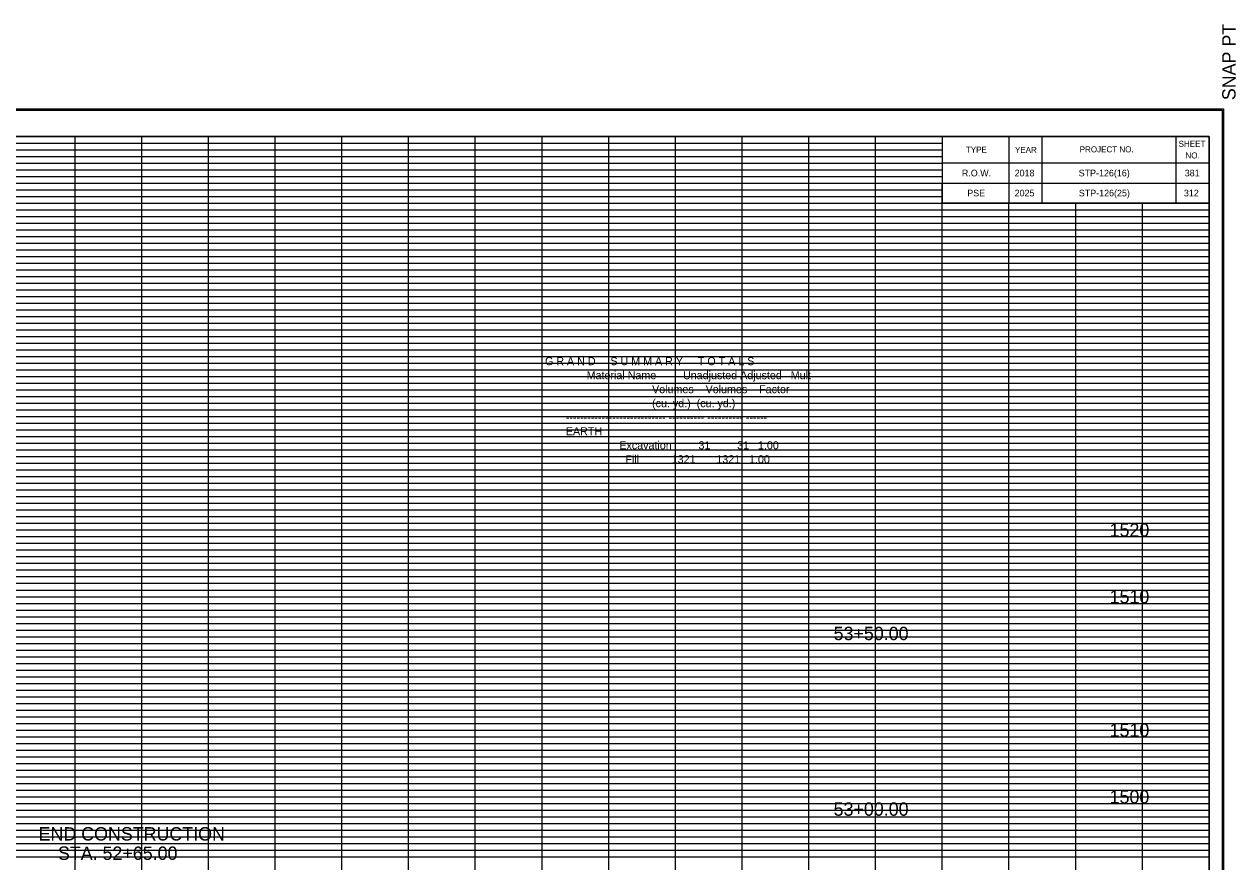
# Model space of a CAD drawing. Extents: x 980 to 1324, y 978 to 1497.
# Drawn here: x 1142.4 to 1324, y 1371.3 to 1496.8 of the extents above; entities that cross this region are included whole.
import ezdxf

# ---------------------------------------------------------------- set-up
doc = ezdxf.new("R2010")
doc.units = 0
for name, color, linetype in [('DESIGN - SCRATCH - User 1', 7, 'Continuous'), ('DESIGN - SHEET - Corner Text', 7, 'Continuous'), ('DESIGN - SHEET - Light Grid', 7, 'Continuous'), ('DESIGN - SHEET - Linework', 7, 'Continuous'), ('DESIGN - SHEET - Plot Shape', 7, 'Continuous'), ('DESIGN - TYPICAL - Text', 7, 'Continuous')]:
    doc.layers.add(name, color=color, linetype=linetype)

# ---------------------------------------------------------------- blocks, each defined once
blk = doc.blocks.new('XSTSHT')
at = {"layer": 'DESIGN - SCRATCH - User 1'}
for p, q in [((28.5, 20.45), (28.5, 20.45)), ((29.24, 20.45), (29.24, 20.45)), ((30.49, 20.45), (30.49, 20.45)), ((31.74, 20.45), (31.74, 20.45)), ((28.5, 20.15), (28.5, 20.15)), ((29.24, 20.15), (29.24, 20.15)), ((30.49, 20.15), (30.49, 20.15)), ((31.74, 20.15), (31.74, 20.15))]:
    blk.add_line(p, q, dxfattribs=at)
at = {"layer": 'DESIGN - SHEET - Light Grid'}
for p, q in [((8, 20.9), (16, 20.9)), ((16, 20.9), (24, 20.9)), ((24, 20.9), (28, 20.9)), ((8, 20.8), (16, 20.8)), ((16, 20.8), (24, 20.8)), ((24, 20.8), (28, 20.8)), ((8, 20.7), (16, 20.7)), ((8, 20.6), (16, 20.6)), ((16, 20.7), (24, 20.7)), ((16, 20.6), (24, 20.6)), ((24, 20.7), (28, 20.7)), ((24, 20.6), (28, 20.6)), ((8, 20.5), (16, 20.5)), ((8, 20.4), (16, 20.4)), ((16, 20.5), (24, 20.5)), ((16, 20.4), (24, 20.4)), ((24, 20.5), (28, 20.5)), ((24, 20.4), (28, 20.4)), ((8, 20.3), (16, 20.3)), ((8, 20.2), (16, 20.2)), ((16, 20.3), (24, 20.3)), ((16, 20.2), (24, 20.2)), ((24, 20.3), (28, 20.3)), ((24, 20.2), (28, 20.2)), ((8, 20.1), (16, 20.1)), ((16, 20.1), (24, 20.1)), ((24, 20.1), (28, 20.1)), ((8, 19.9), (16, 19.9)), ((8, 19.8), (16, 19.8)), ((16, 19.9), (24, 19.9)), ((16, 19.8), (24, 19.8)), ((24, 19.9), (32, 19.9)), ((24, 19.8), (32, 19.8)), ((8, 19.7), (16, 19.7)), ((16, 19.7), (24, 19.7)), ((24, 19.7), (32, 19.7)), ((8, 19.6), (16, 19.6)), ((8, 19.5), (16, 19.5)), ((16, 19.6), (24, 19.6)), ((16, 19.5), (24, 19.5)), ((24, 19.6), (32, 19.6)), ((24, 19.5), (32, 19.5)), ((8, 19.4), (16, 19.4)), ((8, 19.3), (16, 19.3)), ((16, 19.4), (24, 19.4)), ((16, 19.3), (24, 19.3)), ((24, 19.4), (32, 19.4)), ((24, 19.3), (32, 19.3)), ((8, 19.2), (16, 19.2)), ((8, 19.1), (16, 19.1)), ((16, 19.2), (24, 19.2)), ((16, 19.1), (24, 19.1)), ((24, 19.2), (32, 19.2)), ((24, 19.1), (32, 19.1)), ((8, 18.9), (16, 18.9)), ((16, 18.9), (24, 18.9)), ((24, 18.9), (32, 18.9)), ((8, 18.8), (16, 18.8)), ((16, 18.8), (24, 18.8)), ((24, 18.8), (32, 18.8)), ((8, 18.7), (16, 18.7)), ((8, 18.6), (16, 18.6)), ((16, 18.7), (24, 18.7)), ((16, 18.6), (24, 18.6)), ((24, 18.7), (32, 18.7)), ((24, 18.6), (32, 18.6)), ((8, 18.5), (16, 18.5)), ((8, 18.4), (16, 18.4)), ((16, 18.5), (24, 18.5)), ((16, 18.4), (24, 18.4)), ((24, 18.5), (32, 18.5)), ((24, 18.4), (32, 18.4)), ((8, 18.3), (16, 18.3)), ((8, 18.2), (16, 18.2)), ((16, 18.3), (24, 18.3)), ((16, 18.2), (24, 18.2)), ((24, 18.3), (32, 18.3)), ((24, 18.2), (32, 18.2)), ((8, 18.1), (16, 18.1)), ((16, 18.1), (24, 18.1)), ((24, 18.1), (32, 18.1)), ((8, 17.9), (16, 17.9)), ((8, 17.8), (16, 17.8)), ((16, 17.9), (24, 17.9)), ((16, 17.8), (24, 17.8)), ((24, 17.9), (32, 17.9)), ((24, 17.8), (32, 17.8)), ((8, 17.7), (16, 17.7)), ((16, 17.7), (24, 17.7)), ((24, 17.7), (32, 17.7)), ((8, 17.6), (16, 17.6)), ((8, 17.5), (16, 17.5)), ((16, 17.6), (24, 17.6)), ((16, 17.5), (24, 17.5)), ((24, 17.6), (32, 17.6)), ((24, 17.5), (32, 17.5)), ((8, 17.4), (16, 17.4)), ((8, 17.3), (16, 17.3)), ((16, 17.4), (24, 17.4)), ((16, 17.3), (24, 17.3)), ((24, 17.4), (32, 17.4)), ((24, 17.3), (32, 17.3)), ((8, 17.2), (16, 17.2)), ((8, 17.1), (16, 17.1)), ((16, 17.2), (24, 17.2)), ((16, 17.1), (24, 17.1)), ((24, 17.2), (32, 17.2)), ((24, 17.1), (32, 17.1)), ((8, 16.9), (16, 16.9)), ((16, 16.9), (24, 16.9)), ((24, 16.9), (32, 16.9)), ((8, 16.8), (16, 16.8)), ((16, 16.8), (24, 16.8)), ((24, 16.8), (32, 16.8)), ((8, 16.7), (16, 16.7)), ((8, 16.6), (16, 16.6)), ((16, 16.7), (24, 16.7)), ((16, 16.6), (24, 16.6)), ((24, 16.7), (32, 16.7)), ((24, 16.6), (32, 16.6)), ((8, 16.5), (16, 16.5)), ((8, 16.4), (16, 16.4)), ((16, 16.5), (24, 16.5)), ((16, 16.4), (24, 16.4)), ((24, 16.5), (32, 16.5)), ((24, 16.4), (32, 16.4)), ((8, 16.3), (16, 16.3)), ((8, 16.2), (16, 16.2)), ((16, 16.3), (24, 16.3)), ((16, 16.2), (24, 16.2)), ((24, 16.3), (32, 16.3)), ((24, 16.2), (32, 16.2)), ((8, 16.1), (16, 16.1)), ((16, 16.1), (24, 16.1)), ((24, 16.1), (32, 16.1)), ((8, 15.9), (16, 15.9)), ((16, 15.9), (24, 15.9)), ((24, 15.9), (32, 15.9)), ((8, 15.8), (16, 15.8)), ((8, 15.7), (16, 15.7)), ((16, 15.8), (24, 15.8)), ((16, 15.7), (24, 15.7)), ((24, 15.8), (32, 15.8)), ((24, 15.7), (32, 15.7)), ((8, 15.6), (16, 15.6)), ((8, 15.5), (16, 15.5)), ((16, 15.6), (24, 15.6)), ((16, 15.5), (24, 15.5)), ((24, 15.6), (32, 15.6)), ((24, 15.5), (32, 15.5)), ((8, 15.4), (16, 15.4)), ((8, 15.3), (16, 15.3)), ((16, 15.4), (24, 15.4)), ((16, 15.3), (24, 15.3)), ((24, 15.4), (32, 15.4)), ((24, 15.3), (32, 15.3)), ((8, 15.2), (16, 15.2)), ((8, 15.1), (16, 15.1)), ((16, 15.2), (24, 15.2)), ((16, 15.1), (24, 15.1)), ((24, 15.2), (32, 15.2)), ((24, 15.1), (32, 15.1)), ((8, 14.9), (16, 14.9)), ((16, 14.9), (24, 14.9)), ((24, 14.9), (32, 14.9)), ((8, 14.8), (16, 14.8)), ((16, 14.8), (24, 14.8)), ((24, 14.8), (32, 14.8)), ((8, 14.7), (16, 14.7)), ((8, 14.6), (16, 14.6)), ((16, 14.7), (24, 14.7)), ((16, 14.6), (24, 14.6)), ((24, 14.7), (32, 14.7)), ((24, 14.6), (32, 14.6)), ((8, 14.5), (16, 14.5)), ((8, 14.4), (16, 14.4)), ((16, 14.5), (24, 14.5)), ((16, 14.4), (24, 14.4)), ((24, 14.5), (32, 14.5)), ((24, 14.4), (32, 14.4)), ((8, 14.3), (16, 14.3)), ((8, 14.2), (16, 14.2)), ((16, 14.3), (24, 14.3)), ((16, 14.2), (24, 14.2)), ((24, 14.3), (32, 14.3)), ((24, 14.2), (32, 14.2)), ((8, 14.1), (16, 14.1)), ((16, 14.1), (24, 14.1)), ((24, 14.1), (32, 14.1)), ((8, 13.9), (16, 13.9)), ((16, 13.9), (24, 13.9)), ((24, 13.9), (32, 13.9)), ((8, 13.8), (16, 13.8)), ((8, 13.7), (16, 13.7)), ((16, 13.8), (24, 13.8)), ((16, 13.7), (24, 13.7)), ((24, 13.8), (32, 13.8)), ((24, 13.7), (32, 13.7)), ((8, 13.6), (16, 13.6)), ((8, 13.5), (16, 13.5)), ((16, 13.6), (24, 13.6)), ((16, 13.5), (24, 13.5)), ((24, 13.6), (32, 13.6)), ((24, 13.5), (32, 13.5)), ((8, 13.4), (16, 13.4)), ((8, 13.3), (16, 13.3)), ((16, 13.4), (24, 13.4)), ((16, 13.3), (24, 13.3)), ((24, 13.4), (32, 13.4)), ((24, 13.3), (32, 13.3)), ((8, 13.2), (16, 13.2)), ((8, 13.1), (16, 13.1)), ((16, 13.2), (24, 13.2)), ((16, 13.1), (24, 13.1)), ((24, 13.2), (32, 13.2)), ((24, 13.1), (32, 13.1)), ((8, 12.9), (16, 12.9)), ((16, 12.9), (24, 12.9)), ((24, 12.9), (32, 12.9)), ((8, 12.8), (16, 12.8)), ((16, 12.8), (24, 12.8)), ((24, 12.8), (32, 12.8)), ((8, 12.7), (16, 12.7)), ((8, 12.6), (16, 12.6)), ((16, 12.7), (24, 12.7)), ((16, 12.6), (24, 12.6)), ((24, 12.7), (32, 12.7)), ((24, 12.6), (32, 12.6)), ((8, 12.5), (16, 12.5)), ((8, 12.4), (16, 12.4)), ((16, 12.5), (24, 12.5)), ((16, 12.4), (24, 12.4)), ((24, 12.5), (32, 12.5)), ((24, 12.4), (32, 12.4)), ((8, 12.3), (16, 12.3)), ((8, 12.2), (16, 12.2)), ((16, 12.3), (24, 12.3)), ((16, 12.2), (24, 12.2)), ((24, 12.3), (32, 12.3)), ((24, 12.2), (32, 12.2)), ((8, 12.1), (16, 12.1)), ((16, 12.1), (24, 12.1)), ((24, 12.1), (32, 12.1)), ((8, 11.9), (16, 11.9)), ((16, 11.9), (24, 11.9)), ((24, 11.9), (32, 11.9)), ((8, 11.8), (16, 11.8)), ((8, 11.7), (16, 11.7)), ((16, 11.8), (24, 11.8)), ((16, 11.7), (24, 11.7)), ((24, 11.8), (32, 11.8)), ((24, 11.7), (32, 11.7)), ((8, 11.6), (16, 11.6)), ((8, 11.5), (16, 11.5)), ((16, 11.6), (24, 11.6)), ((16, 11.5), (24, 11.5)), ((24, 11.6), (32, 11.6)), ((24, 11.5), (32, 11.5)), ((8, 11.4), (16, 11.4)), ((8, 11.3), (16, 11.3)), ((16, 11.4), (24, 11.4)), ((16, 11.3), (24, 11.3)), ((24, 11.4), (32, 11.4)), ((24, 11.3), (32, 11.3)), ((8, 11.2), (16, 11.2)), ((8, 11.1), (16, 11.1)), ((16, 11.2), (24, 11.2)), ((16, 11.1), (24, 11.1)), ((24, 11.2), (32, 11.2)), ((24, 11.1), (32, 11.1)), ((8, 10.9), (16, 10.9)), ((16, 10.9), (24, 10.9)), ((24, 10.9), (32, 10.9)), ((8, 10.8), (16, 10.8)), ((16, 10.8), (24, 10.8)), ((24, 10.8), (32, 10.8)), ((8, 10.7), (16, 10.7)), ((8, 10.6), (16, 10.6)), ((16, 10.7), (24, 10.7)), ((16, 10.6), (24, 10.6)), ((24, 10.7), (32, 10.7)), ((24, 10.6), (32, 10.6)), ((8, 10.5), (16, 10.5)), ((8, 10.4), (16, 10.4)), ((16, 10.5), (24, 10.5)), ((16, 10.4), (24, 10.4)), ((24, 10.5), (32, 10.5)), ((24, 10.4), (32, 10.4)), ((8, 10.3), (16, 10.3)), ((8, 10.2), (16, 10.2)), ((16, 10.3), (24, 10.3)), ((16, 10.2), (24, 10.2)), ((24, 10.3), (32, 10.3)), ((24, 10.2), (32, 10.2))]:
    blk.add_line(p, q, dxfattribs=at)
at = {"layer": 'DESIGN - SHEET - Linework'}
for p, q in [((-1.823, 21.414), (32.217, 21.414)), ((32.217, 21.414), (32.217, -0.414)), ((15, 0), (15, 21)), ((16, 0), (16, 21)), ((17, 0), (17, 21)), ((18, 0), (18, 21)), ((19, 0), (19, 21)), ((20, 0), (20, 21)), ((21, 0), (21, 21)), ((22, 0), (22, 21)), ((23, 0), (23, 21)), ((24, 0), (24, 21)), ((25, 0), (25, 21)), ((26, 0), (26, 21)), ((27, 0), (27, 21)), ((0, 20), (28, 20)), ((28, 0), (28, 20)), ((29, 0), (29, 20)), ((30, 0), (30, 20)), ((31, 0), (31, 20)), ((0, 19), (32, 19)), ((0, 18), (32, 18)), ((0, 17), (32, 17)), ((0, 16), (32, 16)), ((0, 15), (32, 15)), ((0, 14), (32, 14)), ((0, 13), (32, 13)), ((0, 12), (32, 12)), ((0, 11), (32, 11))]:
    blk.add_line(p, q, dxfattribs=at)
for points in [[(0, 21), (0, 0), (32, 0), (32, 21), (0, 21)], [(28, 21), (28, 20), (32, 20), (32, 21), (31.5, 21), (31.5, 20), (29.5, 20), (29.5, 21), (29, 21), (29, 20), (32, 20), (28, 20), (28, 20.3), (32, 20.3), (32, 20.6), (28, 20.6)]]:
    blk.add_lwpolyline(points, dxfattribs=at)
at = {"layer": 'DESIGN - SHEET - Plot Shape'}
for points in [[(-1.803, 21.394), (32.197, 21.394), (32.197, -0.394), (-1.803, -0.394)], [(-0.85, 21), (32, 21), (32, -0.25), (-0.85, -0.25)]]:
    blk.add_lwpolyline(points, close=True, dxfattribs=at)
at = {"layer": 'DESIGN - SHEET - Corner Text'}
blk.add_text('  SNAP PT', height=0.2, rotation=90, dxfattribs=at).set_placement((32.397, 21.394))
for s, p in [('SHEET', (31.543, 20.843)), ('TYPE', (28.354, 20.756)), ('YEAR', (29.09, 20.752)), ('PROJECT NO.', (30.06, 20.76)), ('NO.', (31.646, 20.669))]:
    blk.add_text(s, height=0.09, dxfattribs=at).set_placement(p)

msp = doc.modelspace()

# ---------------------------------------------------------------- linework, layer by layer
at = {"layer": 'DESIGN - SHEET - Plot Shape'}
msp.add_lwpolyline([(991.5, 1267.5), (1320, 1267.5), (1320, 1480), (991.5, 1480)], close=True, dxfattribs=at)

# ---------------------------------------------------------------- block references
at = {"layer": 'DESIGN - TYPICAL - Text', "xscale": 10, "yscale": 10}
msp.add_blockref('XSTSHT', (1000, 1270), dxfattribs=at)

# ---------------------------------------------------------------- texts
at = {"layer": 'DESIGN - SHEET - Corner Text'}
for s, p in [('R.O.W.', (1282.94, 1474)), ('2018', (1290.85, 1474)), ('STP-126(16)', (1300.45, 1474)), ('381', (1316.35, 1474)), ('PSE', (1283.75, 1471)), ('2025', (1290.85, 1471)), ('STP-126(25)', (1300.47, 1471)), ('312', (1316.22, 1471))]:
    msp.add_text(s, height=1, dxfattribs=at).set_placement(p)
at = {"layer": 'DESIGN - TYPICAL - Text'}
for s, height, p in [(' G R A N D     S U M M A R Y     T O T A L S', 1.2, (1220, 1445.7)), ('               Material Name         Unadjusted Adjusted   Mult', 1.2, (1220, 1443.6)), ('                                     Volumes    Volumes    Factor', 1.2, (1220, 1441.5)), ('                                     (cu. yd.)  (cu. yd.)', 1.2, (1220, 1439.4)), ('        ---------------------------- ---------- ---------- ------', 1.2, (1220, 1437.3)), ('        EARTH', 1.2, (1220, 1435.2)), ('                          Excavation         31         31   1.00', 1.2, (1220, 1433.1)), ('                            Fill           1321       1321   1.00', 1.2, (1220, 1431)), ('     1520     ', 2, (1301.37, 1420)), ('     1510     ', 2, (1301.37, 1410)), ('     53+50.00     ', 2, (1260, 1404.49)), ('     1510     ', 2, (1301.37, 1390)), ('     1500     ', 2, (1301.37, 1380)), ('     53+00.00     ', 2, (1260, 1378.16)), ('END CONSTRUCTION', 2, (1144.53, 1374.45)), ('STA. 52+65.00', 2, (1147.43, 1371.55))]:
    msp.add_text(s, height=height, dxfattribs=at).set_placement(p)

doc.saveas('drawing.dxf')
